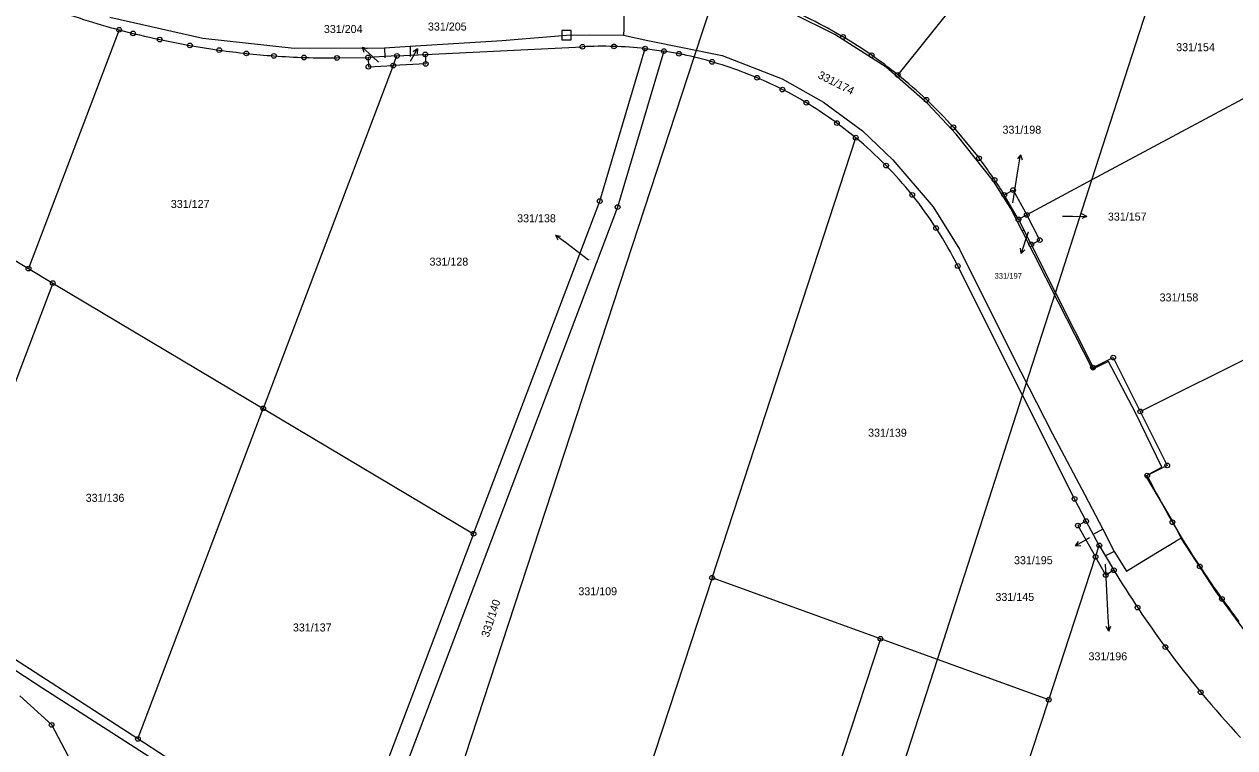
# Model space of a CAD drawing. Extents: x -770973 to -770265, y -1049936 to -1049427.
# Drawn here: x -770766.1 to -770637.6, y -1049630 to -1049553.2 of the extents above; entities that cross this region are included whole.
import ezdxf

# ---------------------------------------------------------------- set-up
doc = ezdxf.new("R2010")
doc.units = 0
for name, color, linetype in [('Vrstva 1', 7, 'Continuous'), ('Vrstva 13', 7, 'Continuous'), ('Vrstva 14', 7, 'Continuous'), ('Vrstva 16', 7, 'Continuous'), ('Vrstva 28', 7, 'Continuous'), ('Vrstva 50', 7, 'Continuous')]:
    doc.layers.add(name, color=color, linetype=linetype)

msp = doc.modelspace()

# ---------------------------------------------------------------- linework, layer by layer
at = {"layer": 'Vrstva 1'}
for p, q in [((-770652.75, -1049569.77), (-770639.88, -1049529.8)), ((-770651.42, -1049531.27), (-770673.36, -1049558.61)), ((-770694.96, -1049556.73), (-770691.9, -1049547.38)), ((-770756.03, -1049553.83), (-770765.65, -1049579.17)), ((-770751.71, -1049554.87), (-770748.52, -1049555.49)), ((-770748.52, -1049555.49), (-770745.4, -1049555.99)), ((-770723.53, -1049556.45), (-770706.84, -1049555.63)), ((-770705, -1049572.01), (-770700.19, -1049555.82)), ((-770698.18, -1049556.09), (-770703.1, -1049572.65)), ((-770700.19, -1049555.82), (-770698.18, -1049556.09)), ((-770732.91, -1049556.82), (-770729.59, -1049556.77)), ((-770726.54, -1049556.6), (-770729.59, -1049556.77)), ((-770729.59, -1049556.77), (-770729.56, -1049557.75)), ((-770726.93, -1049557.62), (-770726.54, -1049556.6)), ((-770723.48, -1049557.45), (-770726.93, -1049557.62)), ((-770726.54, -1049556.6), (-770723.53, -1049556.45)), ((-770724.33, -1049646.32), (-770694.96, -1049556.73)), ((-770723.53, -1049556.45), (-770723.48, -1049557.45)), ((-770629.67, -1049557.4), (-770652.75, -1049569.77)), ((-770726.93, -1049557.62), (-770740.73, -1049594.01)), ((-770729.56, -1049557.75), (-770726.93, -1049557.62)), ((-770693.08, -1049611.99), (-770677.82, -1049565.28)), ((-770667.45, -1049564.18), (-770664.73, -1049567.46)), ((-770784.97, -1049567.65), (-770765.65, -1049579.17)), ((-770652.75, -1049569.77), (-770659.66, -1049573.47)), ((-770656.61, -1049581.75), (-770652.75, -1049569.77)), ((-770662.05, -1049571.36), (-770661.12, -1049570.85)), ((-770660.55, -1049573.96), (-770662.05, -1049571.36)), ((-770661.12, -1049570.85), (-770659.66, -1049573.47)), ((-770703.1, -1049572.65), (-770729.95, -1049643.41)), ((-770718.4, -1049607.32), (-770705, -1049572.01)), ((-770659.66, -1049573.47), (-770660.55, -1049573.96)), ((-770660.55, -1049573.96), (-770659.19, -1049576.61)), ((-770658.29, -1049576.15), (-770659.66, -1049573.47)), ((-770659.19, -1049576.61), (-770658.29, -1049576.15)), ((-770659.19, -1049576.61), (-770656.61, -1049581.75)), ((-770765.65, -1049579.17), (-770763.07, -1049580.71)), ((-770660.11, -1049592.61), (-770666.99, -1049578.9)), ((-770763.07, -1049580.71), (-770775.67, -1049613.91)), ((-770763.07, -1049580.71), (-770740.73, -1049594.01)), ((-770660.11, -1049592.61), (-770656.61, -1049581.75)), ((-770656.61, -1049581.75), (-770652.63, -1049589.69)), ((-770647.61, -1049594.34), (-770624.14, -1049582.59)), ((-770652.63, -1049589.69), (-770650.48, -1049588.62)), ((-770650.48, -1049588.62), (-770647.61, -1049594.34)), ((-770669.15, -1049620.65), (-770660.11, -1049592.61)), ((-770654.59, -1049603.62), (-770660.11, -1049592.61)), ((-770754.04, -1049629.09), (-770740.73, -1049594.01)), ((-770740.73, -1049594.01), (-770718.4, -1049607.32)), ((-770647.61, -1049594.34), (-770644.75, -1049600.06)), ((-770644.75, -1049600.06), (-770646.88, -1049601.15)), ((-770653.36, -1049605.98), (-770654.59, -1049603.62)), ((-770653.36, -1049605.98), (-770654.24, -1049606.45)), ((-770651.96, -1049608.55), (-770653.36, -1049605.98)), ((-770718.4, -1049607.32), (-770731.37, -1049641.52)), ((-770654.24, -1049606.45), (-770652.36, -1049609.77)), ((-770652.36, -1049609.77), (-770651.96, -1049608.55)), ((-770651.96, -1049608.55), (-770650.42, -1049611.19)), ((-770657.33, -1049624.93), (-770652.36, -1049609.77)), ((-770651.27, -1049611.7), (-770652.36, -1049609.77)), ((-770650.42, -1049611.19), (-770651.27, -1049611.7)), ((-770693.08, -1049611.99), (-770706.97, -1049654.36)), ((-770675.2, -1049618.46), (-770693.08, -1049611.99)), ((-770754.04, -1049629.09), (-770773.52, -1049616.5)), ((-770675.2, -1049618.46), (-770688.89, -1049660.26)), ((-770669.15, -1049620.65), (-770675.2, -1049618.46)), ((-770682.94, -1049663.49), (-770669.15, -1049620.65)), ((-770657.33, -1049624.93), (-770669.15, -1049620.65)), ((-770763.19, -1049627.61), (-770766.56, -1049624.51)), ((-770663.4, -1049643.45), (-770657.33, -1049624.93)), ((-770761.06, -1049631.64), (-770763.19, -1049627.61)), ((-770751.11, -1049630.98), (-770754.04, -1049629.09))]:
    msp.add_line(p, q, dxfattribs=at)
for centre, radius, start, end in [((-770732.15, -1049465.46), 91.54, 249.963, 254.8759), ((-770705.43, -1049599.12), 51.7, 59.4615, 68.0688), ((-770728.62, -1049449.46), 107.91, 255.2844, 257.6439), ((-770704.38, -1049597.18), 49.5, 51.1862, 59.3619), ((-770733.01, -1049466.06), 90.78, 262.1553, 265.8369), ((-770704.77, -1049599.67), 44.09, 84.0363, 92.6906), ((-770706.85, -1049608.15), 52.78, 76.9763, 80.5407), ((-770733.42, -1049470.43), 86.39, 265.8963, 270.3367), ((-770704.97, -1049598.41), 42.86, 67.1067, 76.4886), ((-770703.47, -1049596.48), 48.38, 41.8824, 51.5105), ((-770705.08, -1049598.54), 43.03, 59.2086, 67.0518), ((-770706.08, -1049599.68), 44.51, 50.5957, 58.8488), ((-770704.7, -1049597.76), 42.16, 38.763, 50.3825), ((-770702.1, -1049596.01), 47.03, 31.6121, 37.38), ((-770705.05, -1049598.01), 42.59, 26.6585, 38.7351), ((-770557.75, -1049555.99), 99.92, 206.8687, 213.2591), ((-770558.26, -1049555.32), 107.77, 211.2234, 216.4479), ((-770565.39, -1049561.24), 90.64, 213.1334, 217.6631), ((-770557.12, -1049554.45), 109.2, 216.4607, 223.0213)]:
    msp.add_arc(centre, radius, start, end, dxfattribs=at)
at = {"layer": 'Vrstva 13'}
for p, q in [((-770728.48, -1049557.25), (-770729.12, -1049556.67)), ((-770661.13, -1049572.19), (-770660.56, -1049568.57)), ((-770655.87, -1049573.6), (-770654.8, -1049573.61)), ((-770659.51, -1049575.3), (-770659.79, -1049576.14)), ((-770706.18, -1049578.27), (-770708.5, -1049576.52)), ((-770652.99, -1049607.75), (-770653.18, -1049607.86)), ((-770651.35, -1049610.56), (-770651.04, -1049616.16))]:
    msp.add_line(p, q, dxfattribs=at)
at = {"layer": 'Vrstva 16'}
for p, q in [((-770729.12, -1049556.67), (-770730.24, -1049555.67)), ((-770730.24, -1049555.67), (-770730.03, -1049556.19)), ((-770730.24, -1049555.67), (-770729.7, -1049555.82)), ((-770725.09, -1049557.17), (-770724.35, -1049555.86)), ((-770724.35, -1049555.86), (-770724.81, -1049556.18)), ((-770724.35, -1049555.86), (-770724.38, -1049556.42)), ((-770660.33, -1049567.09), (-770660.65, -1049567.54)), ((-770660.56, -1049568.57), (-770660.33, -1049567.09)), ((-770660.33, -1049567.09), (-770660.16, -1049567.62)), ((-770654.8, -1049573.61), (-770653.3, -1049573.63)), ((-770653.3, -1049573.63), (-770653.8, -1049573.37)), ((-770653.3, -1049573.63), (-770653.8, -1049573.87)), ((-770708.5, -1049576.52), (-770709.7, -1049575.62)), ((-770709.7, -1049575.62), (-770709.45, -1049576.12)), ((-770709.7, -1049575.62), (-770709.15, -1049575.72)), ((-770659.79, -1049576.14), (-770660.26, -1049577.56)), ((-770660.26, -1049577.56), (-770660.34, -1049577.01)), ((-770660.26, -1049577.56), (-770659.87, -1049577.17)), ((-770653.18, -1049607.86), (-770654.49, -1049608.6)), ((-770654.49, -1049608.6), (-770654.17, -1049608.13)), ((-770654.49, -1049608.6), (-770653.93, -1049608.57)), ((-770651.04, -1049616.16), (-770650.96, -1049617.66)), ((-770650.96, -1049617.66), (-770651.23, -1049617.17)), ((-770650.96, -1049617.66), (-770650.73, -1049617.14))]:
    msp.add_line(p, q, dxfattribs=at)
at = {"layer": 'Vrstva 28'}
for centre, radius in [((-770756.03, -1049553.83), 0.25), ((-770756.03, -1049553.83), 0.005), ((-770754.54, -1049554.21), 0.25), ((-770754.54, -1049554.21), 0.005), ((-770751.71, -1049554.87), 0.25), ((-770751.71, -1049554.87), 0.005), ((-770679.16, -1049554.59), 0.25), ((-770679.16, -1049554.59), 0.005), ((-770748.52, -1049555.49), 0.25), ((-770748.52, -1049555.49), 0.005), ((-770745.4, -1049555.99), 0.25), ((-770745.4, -1049555.99), 0.005), ((-770742.52, -1049556.34), 0.25), ((-770723.53, -1049556.45), 0.25), ((-770706.84, -1049555.63), 0.25), ((-770706.84, -1049555.63), 0.005), ((-770703.49, -1049555.6), 0.25), ((-770703.49, -1049555.6), 0.005), ((-770700.19, -1049555.82), 0.25), ((-770700.19, -1049555.82), 0.005), ((-770698.18, -1049556.09), 0.25), ((-770698.18, -1049556.09), 0.005), ((-770696.59, -1049556.38), 0.25), ((-770676.14, -1049556.53), 0.25), ((-770742.52, -1049556.34), 0.005), ((-770739.6, -1049556.6), 0.25), ((-770739.6, -1049556.6), 0.005), ((-770736.4, -1049556.77), 0.25), ((-770736.4, -1049556.77), 0.005), ((-770732.91, -1049556.82), 0.25), ((-770732.91, -1049556.82), 0.005), ((-770729.59, -1049556.77), 0.25), ((-770729.56, -1049557.75), 0.25), ((-770729.59, -1049556.77), 0.005), ((-770726.93, -1049557.62), 0.25), ((-770726.54, -1049556.6), 0.25), ((-770726.54, -1049556.6), 0.005), ((-770723.48, -1049557.45), 0.25), ((-770723.53, -1049556.45), 0.005), ((-770723.48, -1049557.45), 0.005), ((-770696.59, -1049556.38), 0.005), ((-770693.07, -1049557.23), 0.25), ((-770693.07, -1049557.23), 0.005), ((-770676.14, -1049556.53), 0.005), ((-770729.56, -1049557.75), 0.005), ((-770726.93, -1049557.62), 0.005), ((-770688.3, -1049558.92), 0.25), ((-770673.36, -1049558.61), 0.25), ((-770673.36, -1049558.61), 0.005), ((-770688.3, -1049558.92), 0.005), ((-770685.61, -1049560.17), 0.25), ((-770685.61, -1049560.17), 0.005), ((-770683.05, -1049561.58), 0.25), ((-770670.31, -1049561.25), 0.25), ((-770670.31, -1049561.25), 0.005), ((-770683.05, -1049561.58), 0.005), ((-770679.82, -1049563.73), 0.25), ((-770679.82, -1049563.73), 0.005), ((-770667.45, -1049564.18), 0.25), ((-770677.82, -1049565.28), 0.25), ((-770677.82, -1049565.28), 0.005), ((-770667.45, -1049564.18), 0.005), ((-770664.73, -1049567.46), 0.25), ((-770664.73, -1049567.46), 0.005), ((-770674.6, -1049568.24), 0.25), ((-770674.6, -1049568.24), 0.005), ((-770663.08, -1049569.76), 0.25), ((-770663.08, -1049569.76), 0.005), ((-770671.83, -1049571.36), 0.25), ((-770671.83, -1049571.36), 0.005), ((-770662.05, -1049571.36), 0.25), ((-770662.05, -1049571.36), 0.005), ((-770661.12, -1049570.85), 0.25), ((-770661.12, -1049570.85), 0.005), ((-770705, -1049572.01), 0.25), ((-770705, -1049572.01), 0.005), ((-770703.1, -1049572.65), 0.25), ((-770703.1, -1049572.65), 0.005), ((-770660.55, -1049573.96), 0.25), ((-770660.55, -1049573.96), 0.005), ((-770659.66, -1049573.47), 0.25), ((-770659.66, -1049573.47), 0.005), ((-770669.29, -1049574.88), 0.25), ((-770669.29, -1049574.88), 0.005), ((-770659.19, -1049576.61), 0.25), ((-770659.19, -1049576.61), 0.005), ((-770658.29, -1049576.15), 0.25), ((-770658.29, -1049576.15), 0.005), ((-770765.65, -1049579.17), 0.25), ((-770765.65, -1049579.17), 0.005), ((-770666.99, -1049578.9), 0.25), ((-770666.99, -1049578.9), 0.005), ((-770763.07, -1049580.71), 0.25), ((-770763.07, -1049580.71), 0.005), ((-770650.48, -1049588.62), 0.25), ((-770652.63, -1049589.69), 0.25), ((-770652.63, -1049589.69), 0.005), ((-770650.48, -1049588.62), 0.005), ((-770740.73, -1049594.01), 0.25), ((-770740.73, -1049594.01), 0.005), ((-770647.61, -1049594.34), 0.25), ((-770647.61, -1049594.34), 0.005), ((-770644.75, -1049600.06), 0.25), ((-770646.88, -1049601.15), 0.25), ((-770646.88, -1049601.15), 0.005), ((-770644.75, -1049600.06), 0.005), ((-770654.59, -1049603.62), 0.25), ((-770654.59, -1049603.62), 0.005), ((-770654.24, -1049606.45), 0.25), ((-770653.36, -1049605.98), 0.25), ((-770653.36, -1049605.98), 0.005), ((-770644.2, -1049606.09), 0.25), ((-770644.2, -1049606.09), 0.005), ((-770718.4, -1049607.32), 0.25), ((-770718.4, -1049607.32), 0.005), ((-770654.24, -1049606.45), 0.005), ((-770651.96, -1049608.55), 0.25), ((-770651.96, -1049608.55), 0.005), ((-770652.36, -1049609.77), 0.25), ((-770652.36, -1049609.77), 0.005), ((-770651.27, -1049611.7), 0.25), ((-770650.42, -1049611.19), 0.25), ((-770650.42, -1049611.19), 0.005), ((-770641.3, -1049610.79), 0.25), ((-770641.3, -1049610.79), 0.005), ((-770693.08, -1049611.99), 0.25), ((-770693.08, -1049611.99), 0.005), ((-770651.27, -1049611.7), 0.005), ((-770638.94, -1049614.23), 0.25), ((-770647.9, -1049615.15), 0.25), ((-770647.9, -1049615.15), 0.005), ((-770638.94, -1049614.23), 0.005), ((-770675.2, -1049618.46), 0.25), ((-770675.2, -1049618.46), 0.005), ((-770644.95, -1049619.35), 0.25), ((-770644.95, -1049619.35), 0.005), ((-770641.2, -1049624.14), 0.25), ((-770641.2, -1049624.14), 0.005), ((-770657.33, -1049624.93), 0.25), ((-770657.33, -1049624.93), 0.005), ((-770763.19, -1049627.61), 0.25), ((-770763.19, -1049627.61), 0.005), ((-770754.04, -1049629.09), 0.25), ((-770754.04, -1049629.09), 0.005)]:
    msp.add_circle(centre, radius, dxfattribs=at)
at = {"layer": 'Vrstva 50'}
for p, q in [((-770702.49, -1049550.86), (-770702.44, -1049553.73)), ((-770680.05, -1049554.34), (-770684.59, -1049552.08)), ((-770757, -1049552.5), (-770747.13, -1049554.72)), ((-770747.13, -1049554.72), (-770737.46, -1049555.77)), ((-770725.14, -1049555.58), (-770715.37, -1049554.97)), ((-770715.37, -1049554.97), (-770708.52, -1049554.4)), ((-770708.02, -1049553.9), (-770709.02, -1049553.9)), ((-770709.02, -1049553.9), (-770709.02, -1049554.9)), ((-770709.02, -1049554.9), (-770708.02, -1049554.9)), ((-770708.52, -1049554.4), (-770706.04, -1049554.35)), ((-770708.02, -1049554.9), (-770708.02, -1049553.9)), ((-770706.04, -1049554.35), (-770702.49, -1049554.39)), ((-770702.44, -1049553.73), (-770702.49, -1049554.39)), ((-770702.49, -1049554.39), (-770699.9, -1049554.95)), ((-770699.9, -1049554.95), (-770691.99, -1049556.54)), ((-770674.58, -1049557.81), (-770680.05, -1049554.34)), ((-770737.46, -1049555.77), (-770727.85, -1049555.74)), ((-770727.85, -1049555.74), (-770725.14, -1049555.58)), ((-770727.85, -1049555.74), (-770727.81, -1049556.79)), ((-770725.14, -1049555.58), (-770725.13, -1049556.65)), ((-770691.99, -1049556.54), (-770685.62, -1049559.02)), ((-770670.17, -1049561.67), (-770674.58, -1049557.81)), ((-770685.62, -1049559.02), (-770681.26, -1049561.5)), ((-770681.26, -1049561.5), (-770677.11, -1049564.56)), ((-770667.15, -1049564.89), (-770670.17, -1049561.67)), ((-770677.11, -1049564.56), (-770673.89, -1049567.63)), ((-770663.2, -1049569.89), (-770667.15, -1049564.89)), ((-770673.89, -1049567.63), (-770669.59, -1049572.63)), ((-770661.36, -1049572.8), (-770663.2, -1049569.89)), ((-770669.59, -1049572.63), (-770666.82, -1049577.11)), ((-770661.36, -1049572.8), (-770661.22, -1049572.79)), ((-770660.14, -1049575.18), (-770661.36, -1049572.8)), ((-770660.14, -1049575.18), (-770659.95, -1049575.03)), ((-770656.33, -1049582.7), (-770660.14, -1049575.18)), ((-770666.82, -1049577.11), (-770661.13, -1049588.47)), ((-770652.69, -1049589.86), (-770656.33, -1049582.7)), ((-770661.13, -1049588.47), (-770656.93, -1049596.71)), ((-770650.97, -1049589.05), (-770652.69, -1049589.86)), ((-770648.11, -1049594.5), (-770650.97, -1049589.05)), ((-770645.31, -1049600.24), (-770648.11, -1049594.5)), ((-770656.93, -1049596.71), (-770653.49, -1049603.18)), ((-770647.02, -1049601.18), (-770645.31, -1049600.24)), ((-770644.24, -1049605.86), (-770647.02, -1049601.18)), ((-770653.49, -1049603.18), (-770651.59, -1049606.83)), ((-770643.28, -1049607.77), (-770644.24, -1049605.86)), ((-770651.59, -1049606.83), (-770652.69, -1049607.45)), ((-770651.59, -1049606.83), (-770650.37, -1049609.21)), ((-770645.79, -1049609.29), (-770643.85, -1049608.09)), ((-770643.28, -1049607.77), (-770643.85, -1049608.09)), ((-770639.54, -1049613.48), (-770643.28, -1049607.77)), ((-770650.37, -1049609.21), (-770651.39, -1049609.71)), ((-770650.37, -1049609.21), (-770649.08, -1049611.3)), ((-770648.32, -1049610.82), (-770645.79, -1049609.29)), ((-770649.08, -1049611.3), (-770648.32, -1049610.82)), ((-770636.24, -1049618.02), (-770639.54, -1049613.48)), ((-770764.12, -1049623.73), (-770775.41, -1049616.43)), ((-770750.85, -1049632.26), (-770764.12, -1049623.73))]:
    msp.add_line(p, q, dxfattribs=at)

# ---------------------------------------------------------------- texts
at = {"layer": 'Vrstva 14'}
for s, height, p in [('331/154', 0.85, (-770643.8, -1049556.1)), ('331/204', 0.05, (-770728.48, -1049557.25)), ('331/205', 0.05, (-770725.09, -1049557.17)), ('331/127', 0.85, (-770750.54, -1049572.74)), ('331/198', 0.05, (-770661.13, -1049572.19)), ('331/157', 0.05, (-770655.87, -1049573.6)), ('331/197', 0.05, (-770659.51, -1049575.3)), ('331/128', 0.85, (-770723.07, -1049578.86)), ('331/138', 0.05, (-770706.18, -1049578.27)), ('331/158', 0.85, (-770645.56, -1049582.66)), ('331/139', 0.85, (-770676.51, -1049597.02)), ('331/136', 0.85, (-770759.58, -1049603.93)), ('331/195', 0.05, (-770652.99, -1049607.75)), ('331/196', 0.05, (-770651.35, -1049610.56)), ('331/109', 0.85, (-770707.27, -1049613.85)), ('331/145', 0.85, (-770662.99, -1049614.45)), ('331/137', 0.85, (-770737.58, -1049617.69))]:
    msp.add_text(s, height=height, dxfattribs=at).set_placement(p)
for s, rotation, p in [('331/174', 333, (-770681.92, -1049558.9)), ('331/140', 72, (-770716.8, -1049618.37))]:
    msp.add_text(s, height=0.85, rotation=rotation, dxfattribs=at).set_placement(p)
at = {"layer": 'Vrstva 16'}
for s, height, p in [('331/204', 0.85, (-770734.29, -1049554.17)), ('331/205', 0.85, (-770723.24, -1049553.91)), ('331/198', 0.85, (-770662.24, -1049564.86)), ('331/138', 0.85, (-770713.77, -1049574.26)), ('331/157', 0.85, (-770651.05, -1049574.08)), ('331/197', 0.6, (-770663.08, -1049580.25)), ('331/195', 0.85, (-770661.02, -1049610.55)), ('331/196', 0.85, (-770653.11, -1049620.75))]:
    msp.add_text(s, height=height, dxfattribs=at).set_placement(p)

doc.saveas('drawing.dxf')
